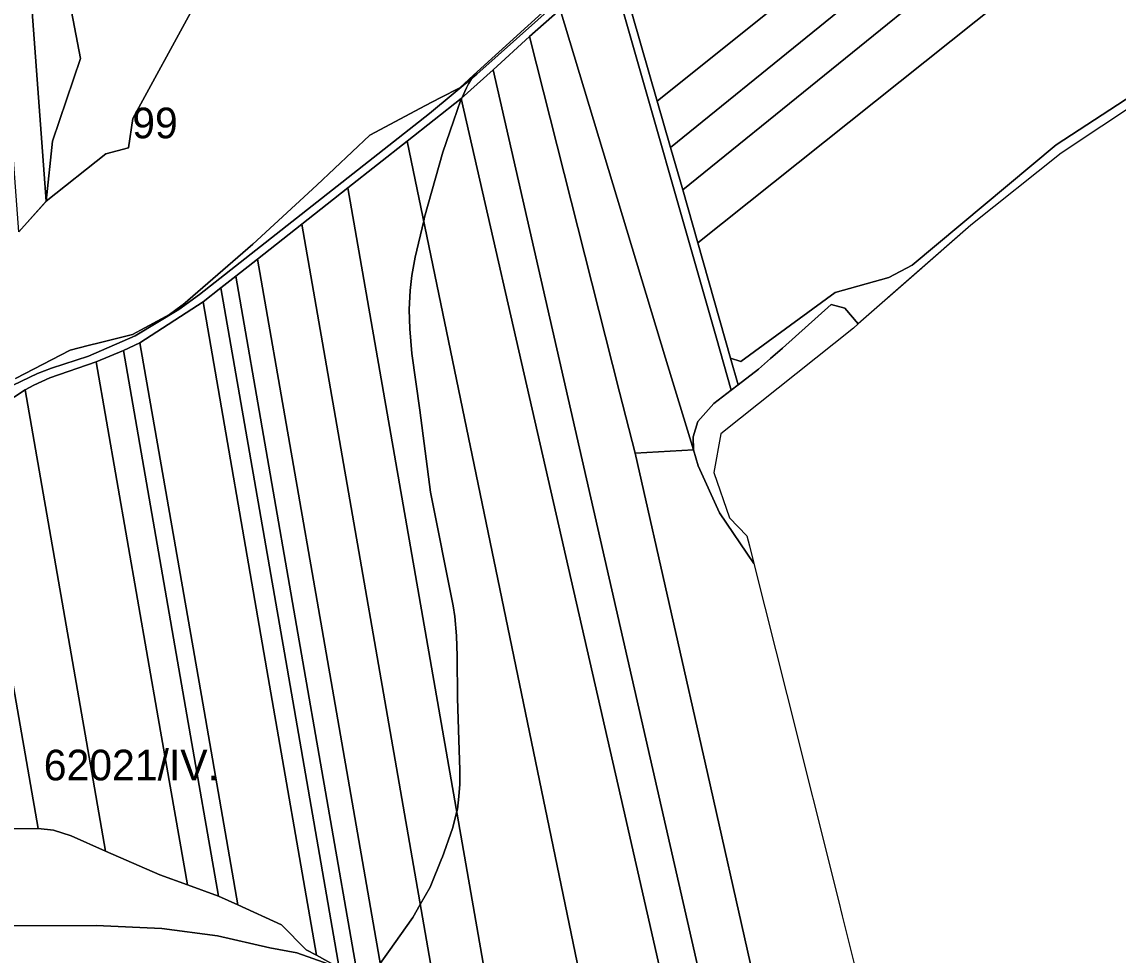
# Model space of a CAD drawing. Extents: x -521939 to -516426, y -1197857 to -1189551.
# Drawn here: x -518510 to -517973, y -1193004 to -1192547 of the extents above; entities that cross this region are included whole.
import ezdxf

# ---------------------------------------------------------------- set-up
doc = ezdxf.new("R2010")
doc.units = 0
for name, color, linetype in [('95610013', 7, 'Continuous'), ('95620013', 7, 'Continuous'), ('95640013', 7, 'Continuous'), ('95660013', 7, 'Continuous')]:
    doc.layers.add(name, color=color, linetype=linetype)

msp = doc.modelspace()

# ---------------------------------------------------------------- linework, layer by layer
at = {"layer": '95610013'}
for points in [[(-518506.43, -1192334.55), (-518501.93, -1192355.15), (-518498.06, -1192386.81), (-518502.71, -1192408.4), (-518490.86, -1192514.75), (-518481.29, -1192565.14), (-518494.97, -1192605.71), (-518498.14, -1192635.04), (-518508, -1192500.15), (-518520.99, -1192322.44), (-518505.72, -1192320.55)], [(-518536.05, -1192324.32), (-518520.99, -1192322.44), (-518508, -1192500.15), (-518498.14, -1192635.04), (-518511.48, -1192649.99), (-518522.47, -1192504.32)], [(-517979.17, -1192355.85), (-517947.12, -1192384.46), (-518062.13, -1192476.65), (-518198.61, -1192586.05), (-518210.9, -1192543.36), (-518070.51, -1192429.76)], [(-517947.12, -1192384.46), (-517933.09, -1192398.78), (-518052.55, -1192495.67), (-518192.07, -1192608.83), (-518198.61, -1192586.05), (-518062.13, -1192476.65)], [(-518192.07, -1192608.83), (-518052.55, -1192495.67), (-517933.09, -1192398.78), (-517920.9, -1192414.69), (-518047.2, -1192516.99), (-518186.13, -1192629.52)], [(-517920.9, -1192414.69), (-517912.56, -1192427.26), (-517916.41, -1192439.93), (-517952.89, -1192475.46), (-518042.44, -1192546.79), (-518178.78, -1192655.39), (-518186.13, -1192629.52), (-518047.2, -1192516.99)], [(-518178.78, -1192655.39), (-518042.44, -1192546.79), (-517952.89, -1192475.46), (-517966.33, -1192499.14), (-517944.59, -1192511.06), (-517933.87, -1192518.63), (-517925.61, -1192526.94), (-517916.64, -1192551.13), (-518003.1, -1192607.37), (-518073.65, -1192666.41), (-518085.13, -1192672.38), (-518111.4, -1192679.81), (-518157.63, -1192713.61), (-518162.65, -1192711.95)], [(-518180.89, -1192756.84), (-518194.49, -1192711.97), (-518246.25, -1192541.2), (-518228.12, -1192524.84), (-518225.97, -1192523.73), (-518223.2, -1192523.8), (-518220.82, -1192525.2), (-518219.42, -1192527.58), (-518169.62, -1192702.12), (-518162.35, -1192727.6), (-518170.92, -1192734.22), (-518178.69, -1192742.92), (-518181.04, -1192750.48)], [(-518180.89, -1192756.84), (-518209.44, -1192758.46), (-518217.03, -1192728.56), (-518261.25, -1192554.36), (-518246.25, -1192541.2), (-518194.49, -1192711.97)], [(-518158.26, -1193099.67), (-518198.65, -1192922.73), (-518238.83, -1192746.71), (-518279.01, -1192570.69), (-518261.25, -1192554.36), (-518217.03, -1192728.56), (-518209.44, -1192758.46), (-518173.86, -1192915.92), (-518132.24, -1193100.11), (-518128.95, -1193114.67)], [(-518179.48, -1193089.1), (-518215.17, -1192932.78), (-518254.65, -1192759.86), (-518294.63, -1192584.75), (-518279.01, -1192570.69), (-518238.83, -1192746.71), (-518198.65, -1192922.73), (-518158.26, -1193099.67)], [(-518225.89, -1193065.68), (-518247.64, -1192960.63), (-518284.38, -1192783.18), (-518321.12, -1192605.73), (-518294.63, -1192584.75), (-518254.65, -1192759.86), (-518215.17, -1192932.78), (-518179.48, -1193089.1)], [(-518350.16, -1192628.53), (-518321.12, -1192605.73), (-518284.38, -1192783.18), (-518247.64, -1192960.63), (-518225.89, -1193065.68), (-518278.49, -1193039.24)], [(-518306.65, -1193026.04), (-518372.77, -1192646.35), (-518360.29, -1192636.5), (-518350.16, -1192628.53), (-518278.49, -1193039.24), (-518290.64, -1193033.2), (-518301.5, -1193027.7)], [(-518332.79, -1193017.61), (-518362.85, -1192845.05), (-518394.49, -1192663.42), (-518372.77, -1192646.35), (-518306.65, -1193026.04)], [(-518345.74, -1193013.45), (-518375.39, -1192842.99), (-518405.16, -1192671.84), (-518394.49, -1192663.42), (-518362.85, -1192845.05), (-518332.79, -1193017.61)], [(-518354.48, -1193010.65), (-518381.33, -1192856.31), (-518412.43, -1192677.54), (-518405.16, -1192671.84), (-518375.39, -1192842.99), (-518345.74, -1193013.45)], [(-518421.2, -1192684.43), (-518412.43, -1192677.54), (-518381.33, -1192856.31), (-518354.48, -1193010.65), (-518365.62, -1193004.33), (-518389.89, -1192864.64)], [(-518452.17, -1192704.44), (-518421.2, -1192684.43), (-518389.89, -1192864.64), (-518365.62, -1193004.33), (-518370.63, -1193001.75), (-518382.7, -1192989.47), (-518404.12, -1192979.78), (-518421.36, -1192880.99)], [(-518473.54, -1192713.82), (-518460.22, -1192708.28), (-518429.09, -1192886.74), (-518413.6, -1192975.54), (-518428.88, -1192969.95), (-518443.15, -1192888.11)], [(-518404.12, -1192979.78), (-518413.6, -1192975.54), (-518429.09, -1192886.74), (-518460.22, -1192708.28), (-518452.17, -1192704.44), (-518421.36, -1192880.99)], [(-518443.15, -1192888.11), (-518428.88, -1192969.95), (-518442.41, -1192965.03), (-518469.02, -1192953.53), (-518477.72, -1192903.66), (-518508.45, -1192727.51), (-518504.2, -1192725.16), (-518496.32, -1192721.61), (-518473.54, -1192713.82)], [(-518508.45, -1192727.51), (-518477.72, -1192903.66), (-518469.02, -1192953.53), (-518485.76, -1192945.93), (-518494.49, -1192943.25), (-518502, -1192942.29), (-518535.64, -1192750.15), (-518525.8, -1192740.06), (-518518.9, -1192734.37)], [(-518502, -1192942.29), (-518519.63, -1192942.55), (-518550.24, -1192766.43), (-518535.64, -1192750.15)], [(-518128.95, -1193114.67), (-518132.24, -1193100.11), (-518173.86, -1192915.92), (-518209.44, -1192758.46), (-518180.89, -1192756.84), (-518178.51, -1192764.73), (-518168.14, -1192787.68), (-518151.23, -1192812.5), (-518135.12, -1192876.72), (-518109.82, -1192977.58), (-518107.93, -1192985.11), (-518095.16, -1193036.02), (-518078.88, -1193100.92), (-518069.18, -1193139.58), (-518067.56, -1193146.04)], [(-518441.46, -1192991.31), (-518473.62, -1192989.89), (-518515.05, -1192990), (-518518.64, -1192955.67), (-518520.44, -1192948.52), (-518525.77, -1192940.63), (-518533.4, -1192935.15), (-518519.63, -1192942.55), (-518502, -1192942.29), (-518494.49, -1192943.25), (-518485.76, -1192945.93), (-518469.02, -1192953.53), (-518442.41, -1192965.03), (-518428.88, -1192969.95), (-518413.6, -1192975.54), (-518404.12, -1192979.78), (-518382.7, -1192989.47), (-518370.63, -1193001.75), (-518365.62, -1193004.33), (-518354.48, -1193010.65), (-518375.31, -1193003.18), (-518388.43, -1193000.81), (-518414.09, -1192994.92)]]:
    msp.add_lwpolyline(points, close=True, dxfattribs=at)
at = {"layer": '95620013'}
for points in [[(-518246.71, -1192536.92), (-518287.07, -1192572.91), (-518310.17, -1192592.05), (-518422.94, -1192680.71), (-518433.02, -1192688.13), (-518454.48, -1192700.99), (-518477.39, -1192711.04), (-518495.46, -1192716.79), (-518502.35, -1192719.43), (-518514.28, -1192725.19)], [(-518511.48, -1192649.99), (-518498.14, -1192635.04), (-518468.77, -1192611.88), (-518457.8, -1192608.96), (-518455.63, -1192594.52), (-518426.41, -1192540.96)]]:
    msp.add_lwpolyline(points, dxfattribs=at)
at = {"layer": '95640013'}
for points in [[(-518491.21, -1192318.79), (-518488.1, -1192356.89), (-518470.37, -1192375.68), (-518458.28, -1192465.08), (-518450.59, -1192507.65), (-518440.4, -1192522.41), (-518431.68, -1192526.89), (-518402.81, -1192529.91), (-518426.41, -1192540.96), (-518455.63, -1192594.52), (-518457.8, -1192608.96), (-518468.77, -1192611.88), (-518498.14, -1192635.04), (-518494.97, -1192605.71), (-518481.29, -1192565.14), (-518490.86, -1192514.75), (-518502.71, -1192408.4), (-518498.06, -1192386.81), (-518501.93, -1192355.15), (-518506.43, -1192334.55), (-518505.72, -1192320.55)], [(-518228.12, -1192524.84), (-518212.63, -1192511.08), (-518216.5, -1192519.92), (-518216.3, -1192523.95), (-518210.9, -1192543.36), (-518198.61, -1192586.05), (-518192.07, -1192608.83), (-518186.13, -1192629.52), (-518178.78, -1192655.39), (-518162.65, -1192711.95), (-518158.94, -1192724.96), (-518162.35, -1192727.6), (-518169.62, -1192702.12), (-518219.42, -1192527.58), (-518220.82, -1192525.2), (-518223.2, -1192523.8), (-518225.97, -1192523.73)], [(-517914.33, -1192554.36), (-517920.39, -1192558.37), (-518000.71, -1192611.51), (-518044.98, -1192646.87), (-518100.15, -1192695.18), (-518106.7, -1192687.4), (-518113.39, -1192685.66), (-518137.16, -1192707.07), (-518143.03, -1192712.13), (-518149.04, -1192717.31), (-518158.94, -1192724.96), (-518162.65, -1192711.95), (-518157.63, -1192713.61), (-518111.4, -1192679.81), (-518085.13, -1192672.38), (-518073.65, -1192666.41), (-518003.1, -1192607.37), (-517916.64, -1192551.13)], [(-518100.15, -1192695.18), (-518102.47, -1192697.21), (-518167.4, -1192749.03), (-518170.83, -1192768.02), (-518163.11, -1192790.22), (-518154.62, -1192798.99), (-518153.39, -1192803.9), (-518151.23, -1192812.5), (-518168.14, -1192787.68), (-518178.51, -1192764.73), (-518180.89, -1192756.84), (-518181.04, -1192750.48), (-518178.69, -1192742.92), (-518170.92, -1192734.22), (-518162.35, -1192727.6), (-518158.94, -1192724.96), (-518149.04, -1192717.31), (-518143.03, -1192712.13), (-518137.16, -1192707.07), (-518113.39, -1192685.66), (-518106.7, -1192687.4)]]:
    msp.add_lwpolyline(points, close=True, dxfattribs=at)
for points in [[(-518246.25, -1192541.2), (-518261.25, -1192554.36), (-518279.01, -1192570.69), (-518294.63, -1192584.75), (-518321.12, -1192605.73), (-518350.16, -1192628.53), (-518360.29, -1192636.5), (-518372.77, -1192646.35), (-518394.49, -1192663.42), (-518405.16, -1192671.84), (-518412.43, -1192677.54), (-518421.2, -1192684.43), (-518452.17, -1192704.44), (-518460.22, -1192708.28), (-518473.54, -1192713.82), (-518496.32, -1192721.61), (-518504.2, -1192725.16), (-518508.45, -1192727.51), (-518518.9, -1192734.37)], [(-518514.28, -1192725.19), (-518502.35, -1192719.43), (-518495.46, -1192716.79), (-518477.39, -1192711.04), (-518454.48, -1192700.99), (-518433.02, -1192688.13), (-518422.94, -1192680.71), (-518310.17, -1192592.05), (-518287.07, -1192572.91), (-518246.71, -1192536.92)], [(-518515.05, -1192990), (-518473.62, -1192989.89), (-518441.46, -1192991.31), (-518414.09, -1192994.92), (-518388.43, -1193000.81), (-518375.31, -1193003.18), (-518354.48, -1193010.65)]]:
    msp.add_lwpolyline(points, dxfattribs=at)
at = {"layer": '95660013'}
for points in [[(-518490.84, -1192514.76), (-518481.29, -1192565.14), (-518494.97, -1192605.71), (-518498.14, -1192635.04), (-518498.4, -1192635.34), (-518498.43, -1192635.55), (-518510.23, -1192648.59)], [(-518510.23, -1192648.59), (-518498.43, -1192635.55), (-518498.4, -1192635.34), (-518498.14, -1192635.04), (-518494.97, -1192605.71), (-518481.29, -1192565.14), (-518490.84, -1192514.76)], [(-518249.55, -1192537.96), (-518288.66, -1192573.4), (-518295.38, -1192579.49), (-518304.93, -1192584.4), (-518312.25, -1192588.16), (-518339.4, -1192602.66), (-518365.36, -1192627.27), (-518396.85, -1192656.14), (-518431.15, -1192685.75), (-518431.43, -1192685.96), (-518437.6, -1192690.58), (-518455.72, -1192700.35), (-518471.4, -1192704.29), (-518477.44, -1192705.81), (-518486.27, -1192708.03), (-518513.07, -1192721.98)], [(-518334.39, -1193008.44), (-518330.25, -1193002.82), (-518318.35, -1192986.02), (-518314.74, -1192979.6), (-518309.95, -1192971.09), (-518304.12, -1192956.86), (-518304.07, -1192956.72), (-518298.87, -1192942.34), (-518296.84, -1192934.1), (-518296.54, -1192932.89), (-518295.84, -1192926.6), (-518295.37, -1192920.65), (-518295.37, -1192913.65), (-518295.84, -1192899.07), (-518296.42, -1192878.54), (-518296.65, -1192857.89), (-518297, -1192847.98), (-518297.82, -1192838.53), (-518298.64, -1192833.28), (-518309.72, -1192777.65), (-518314.97, -1192737.4), (-518318.82, -1192709.64), (-518319.87, -1192697.63), (-518320.22, -1192688.18), (-518319.75, -1192678.73), (-518318.93, -1192671.39), (-518317.18, -1192662.41), (-518313.05, -1192644.72), (-518312.63, -1192642.93), (-518303.65, -1192610.97), (-518298.4, -1192595.8), (-518294.79, -1192585.42), (-518294.58, -1192584.96), (-518294.38, -1192584.53), (-518292.1, -1192579.52), (-518291.17, -1192577.49), (-518289.69, -1192575.08), (-518288.66, -1192573.4), (-518249.55, -1192537.96)], [(-517920.39, -1192558.37), (-518000.71, -1192611.51), (-518044.98, -1192646.87)], [(-518513.07, -1192721.98), (-518486.27, -1192708.03), (-518477.44, -1192705.81), (-518471.4, -1192704.29), (-518455.72, -1192700.35), (-518437.6, -1192690.58), (-518431.43, -1192685.96), (-518431.15, -1192685.75), (-518396.85, -1192656.14), (-518365.36, -1192627.27), (-518339.4, -1192602.66), (-518312.25, -1192588.16), (-518304.93, -1192584.4), (-518295.38, -1192579.49), (-518288.66, -1192573.4), (-518289.69, -1192575.08), (-518291.17, -1192577.49), (-518292.1, -1192579.52), (-518294.38, -1192584.53), (-518294.58, -1192584.96), (-518294.79, -1192585.42), (-518298.4, -1192595.8), (-518303.65, -1192610.97), (-518312.63, -1192642.93), (-518313.05, -1192644.72), (-518317.18, -1192662.41), (-518318.93, -1192671.39), (-518319.75, -1192678.73), (-518320.22, -1192688.18), (-518319.87, -1192697.63), (-518318.82, -1192709.64), (-518314.97, -1192737.4), (-518309.72, -1192777.65), (-518298.64, -1192833.28), (-518297.82, -1192838.53), (-518297, -1192847.98), (-518296.65, -1192857.89), (-518296.42, -1192878.54), (-518295.84, -1192899.07), (-518295.37, -1192913.65), (-518295.37, -1192920.65), (-518295.84, -1192926.6), (-518296.54, -1192932.89), (-518296.84, -1192934.1), (-518298.87, -1192942.34), (-518304.07, -1192956.72), (-518304.12, -1192956.86), (-518309.95, -1192971.09), (-518314.74, -1192979.6), (-518318.35, -1192986.02), (-518330.25, -1193002.82), (-518334.39, -1193008.44)], [(-518044.98, -1192646.87), (-518072.8, -1192671.23), (-518100.15, -1192695.18), (-518102.47, -1192697.21), (-518167.4, -1192749.03), (-518170.83, -1192768.02), (-518163.11, -1192790.22), (-518154.62, -1192798.99), (-518153.39, -1192803.9), (-518151.23, -1192812.5), (-518135.12, -1192876.72), (-518109.82, -1192977.58), (-518107.93, -1192985.11), (-518095.16, -1193036.02)]]:
    msp.add_lwpolyline(points, dxfattribs=at)

# ---------------------------------------------------------------- texts
for s, p in [('99', (-518455.9, -1192604.24)), ('62021/IV.', (-518499.27, -1192918.77))]:
    msp.add_text(s, height=15, rotation=0, dxfattribs=at).set_placement(p)

doc.saveas('drawing.dxf')
